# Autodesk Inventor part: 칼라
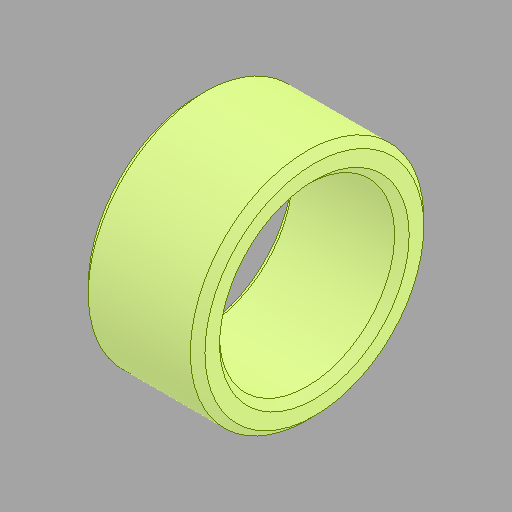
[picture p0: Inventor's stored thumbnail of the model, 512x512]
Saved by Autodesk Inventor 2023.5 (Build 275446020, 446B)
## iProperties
Created: 2026-03
Part Number: 칼라
Material: 강철, 연강
Document SubType Name: Modeling
Designer: mirae
Density: 7.85 g/cm^3
Appearance: 기본값
Author: jhkim
Sending System: Autodesk Inventor 2026
Preprocessor: ST-DEVELOPER v20.1
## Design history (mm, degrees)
node "칼라1"
node "솔리드2"
node "솔리드1"
